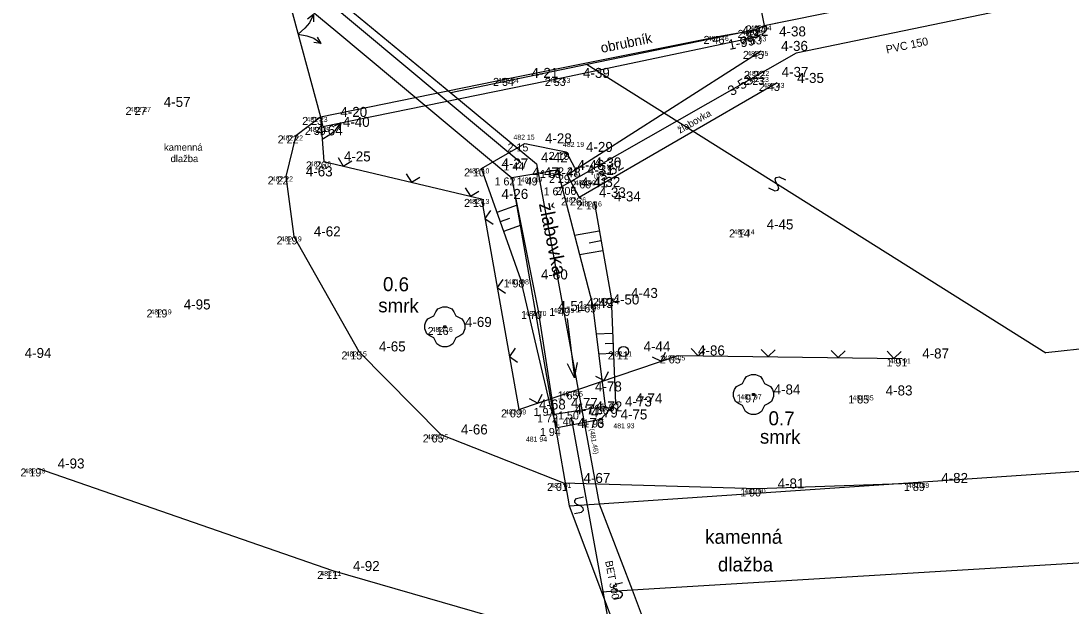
# Model space of a CAD drawing. Extents: x -651478 to -651308, y -994378 to -994071.
# Drawn here: x -651409.01 to -651388.03, y -994292.61 to -994280.91 of the extents above; entities that cross this region are included whole.
import ezdxf

# ---------------------------------------------------------------- set-up
doc = ezdxf.new("R2010")
doc.units = 0
for name, color, linetype in [('13_POPIS_POLOHOPISU', 7, 'Continuous'), ('14_ROZHRANI_PLOCH', 7, 'Continuous'), ('18_TECKY_BODU', 7, 'Continuous'), ('19_CISLA_BODU', 7, 'Continuous'), ('20_REDUKOVANE_VYSKY_BODU', 7, 'Continuous'), ('22_JEDNOTL_STROMY', 7, 'Continuous'), ('23_BREHOVA_CARA', 7, 'Continuous'), ('25_CHODNIKY', 7, 'Continuous'), ('26_PLOTY', 7, 'Continuous'), ('29_PROPUSTKY', 7, 'Continuous'), ('34_KANAL-VEDENI', 7, 'Continuous'), ('52_UPLNE_VYSKY_NADZEMNICH_ZNAKU', 7, 'Continuous'), ('55_SVAHOVE_CARY', 7, 'Continuous'), ('61_UPLNE_VYSKY_BODU', 7, 'Continuous'), ('_KM', 7, 'Continuous'), ('rybnik oprava', 7, 'Continuous')]:
    doc.layers.add(name, color=color, linetype=linetype)

# ---------------------------------------------------------------- blocks, each defined once
blk = doc.blocks.new('POINT_DISPLAY')
blk.add_line((0, 0), (0, 0))
blk = doc.blocks.new('Z58')
for p, q in [((-0.3, 0.4), (-0.16, 0.28)), ((-0.3, 0.4), (-0.24, 0.26)), ((-0.3, 0.4), (-0.16, 0.36)), ((-0.16, 0.28), (-0.08, 0.16)), ((0.08, 0.16), (0.16, 0.28)), ((0.16, 0.28), (0.3, 0.4)), ((0.3, 0.4), (0.16, 0.36)), ((0.3, 0.4), (0.24, 0.26)), ((-0.08, 0.16), (0, 0)), ((0, 0), (0.08, 0.16))]:
    blk.add_line(p, q)
blk = doc.blocks.new('Z212')
for p, q in [((-0.14, 0.14), (0, 0)), ((0, 0), (0.14, 0.14))]:
    blk.add_line(p, q)
blk = doc.blocks.new('Z313')
for p, q in [((-0.34, 0.16), (-0.22, 0.22)), ((-0.22, 0.22), (-0.18, 0.3)), ((-0.18, 0.3), (-0.14, 0.36)), ((-0.14, 0.36), (-0.04, 0.4)), ((-0.04, 0.4), (0.04, 0.4)), ((0.04, 0.4), (0.14, 0.36)), ((0.14, 0.36), (0.18, 0.3)), ((0.18, 0.3), (0.22, 0.22)), ((0.22, 0.22), (0.34, 0.16)), ((-0.4, 0.04), (-0.38, 0.1)), ((-0.4, -0.04), (-0.4, 0.04)), ((-0.38, 0.1), (-0.34, 0.16)), ((-0.02, -0.02), (-0.02, 0.02)), ((-0.02, 0.02), (0.02, 0.02)), ((0.02, 0.02), (0.02, -0.02)), ((0.34, 0.16), (0.38, 0.1)), ((0.38, 0.1), (0.4, 0.04)), ((0.4, 0.04), (0.4, -0.04)), ((-0.36, -0.14), (-0.4, -0.04)), ((-0.3, -0.18), (-0.36, -0.14)), ((-0.22, -0.22), (-0.3, -0.18)), ((0.02, -0.02), (-0.02, -0.02)), ((0.3, -0.18), (0.22, -0.22)), ((0.36, -0.14), (0.3, -0.18)), ((0.4, -0.04), (0.36, -0.14)), ((-0.16, -0.34), (-0.22, -0.22)), ((-0.1, -0.38), (-0.16, -0.34)), ((-0.04, -0.4), (-0.1, -0.38)), ((0.04, -0.4), (-0.04, -0.4)), ((0.1, -0.38), (0.04, -0.4)), ((0.16, -0.34), (0.1, -0.38)), ((0.22, -0.22), (0.16, -0.34))]:
    blk.add_line(p, q)
blk = doc.blocks.new('Z105')
for radius in [0.1, 0.002]:
    blk.add_circle((0, 0), radius)
blk = doc.blocks.new('Z802')
for p, q in [((-0.6, 0), (0.6, 0)), ((0.6, 0), (0.3, 0.1)), ((0.6, 0), (0.3, -0.1))]:
    blk.add_line(p, q)
blk = doc.blocks.new('Z218')
for p, q in [((-0.04, 0.14), (-0.08, 0.1)), ((-0.08, 0.1), (-0.08, 0.06)), ((-0.08, 0.06), (-0.04, 0.02)), ((0.1, 0.16), (-0.04, 0.14)), ((-0.04, 0.02), (0.04, -0.02)), ((0.04, -0.14), (-0.1, -0.16)), ((0.04, -0.02), (0.08, -0.06)), ((0.08, -0.1), (0.04, -0.14)), ((0.08, -0.06), (0.08, -0.1))]:
    blk.add_line(p, q)

msp = doc.modelspace()

# ---------------------------------------------------------------- linework, layer by layer
at = {"layer": '14_ROZHRANI_PLOCH'}
for p, q in [((-651403.52, -994283.2), (-651403.03, -994282.83)), ((-651403.52, -994283.2), (-651403.72, -994284.02)), ((-651403.72, -994284.02), (-651403.56, -994285.22)), ((-651403.56, -994285.22), (-651402.26, -994287.52)), ((-651402.26, -994287.52), (-651400.62, -994289.18)), ((-651400.62, -994289.18), (-651398.17, -994290.15)), ((-651402.78, -994291.91), (-651408.68, -994289.86)), ((-651398.17, -994290.15), (-651394.29, -994290.26)), ((-651394.29, -994290.26), (-651391.02, -994290.15)), ((-651398.36, -994293.18), (-651402.78, -994291.91))]:
    msp.add_line(p, q, dxfattribs=at)
at = {"layer": '23_BREHOVA_CARA'}
for p, q in [((-651394.16, -994281), (-651393.768, -994280.921)), ((-651398.1, -994283.99), (-651394.22, -994281.51)), ((-651393.9, -994282.15), (-651397.86, -994284.44)), ((-651399.2, -994284.04), (-651398.29, -994283.89)), ((-651398.29, -994283.89), (-651397.59, -994286.58)), ((-651398.1, -994283.99), (-651397.86, -994284.44)), ((-651398.67, -994286.71), (-651399.2, -994284.04)), ((-651398.35, -994288.78), (-651398.67, -994286.71)), ((-651397.59, -994286.58), (-651397.34, -994288.62)), ((-651397.34, -994288.62), (-651398.35, -994288.78))]:
    msp.add_line(p, q, dxfattribs=at)
at = {"layer": '25_CHODNIKY'}
for p, q in [((-651394.33, -994281.09), (-651394.16, -994281)), ((-651399.21, -994282.05), (-651395.01, -994281.21)), ((-651394.26, -994281.22), (-651398.18, -994282.05)), ((-651395.01, -994281.21), (-651394.33, -994281.09)), ((-651403.03, -994282.83), (-651399.21, -994282.05)), ((-651398.18, -994282.05), (-651402.98, -994283.03)), ((-651403.03, -994282.83), (-651402.98, -994283.03))]:
    msp.add_line(p, q, dxfattribs=at)
at = {"layer": '26_PLOTY'}
for p, q in [((-651403.92, -994279.52), (-651403.03, -994282.83)), ((-651403.03, -994282.83), (-651402.96, -994283.72)), ((-651402.62, -994282.947), (-651402.756, -994283.015)), ((-651402.729, -994283.093), (-651402.62, -994282.947)), ((-651402.62, -994282.947), (-651402.649, -994283.087)), ((-651402.842, -994283.184), (-651402.729, -994283.093)), ((-651402.995, -994283.275), (-651402.842, -994283.184)), ((-651402.96, -994283.72), (-651399.81, -994284.47)), ((-651399.81, -994284.47), (-651399.06, -994288.68)), ((-651399.06, -994288.68), (-651395.88, -994287.6)), ((-651395.88, -994287.6), (-651391.4, -994287.66))]:
    msp.add_line(p, q, dxfattribs=at)
at = {"layer": '29_PROPUSTKY'}
for p, q in [((-651407.5, -994276.66), (-651399.02, -994283.74)), ((-651398.02, -994288.84), (-651396.42, -994297.57))]:
    msp.add_line(p, q, dxfattribs=at)
at = {"layer": '34_KANAL-VEDENI'}
for p, q in [((-651389.625, -994280.75), (-651393.522, -994281.556)), ((-651393.522, -994281.556), (-651398.24, -994284.25))]:
    msp.add_line(p, q, dxfattribs=at)
at = {"layer": '55_SVAHOVE_CARY'}
for p, q in [((-651399.81, -994283.86), (-651398.94, -994283.36)), ((-651398.94, -994283.36), (-651398.12, -994283.53)), ((-651398.12, -994283.53), (-651397.95, -994283.84)), ((-651399.02, -994286.08), (-651399.81, -994283.86)), ((-651399.498, -994284.736), (-651399.091, -994284.591)), ((-651397.56, -994284.52), (-651397.22, -994286.45)), ((-651399.431, -994284.924), (-651399.241, -994284.856)), ((-651399.364, -994285.112), (-651399.012, -994284.987)), ((-651397.455, -994285.114), (-651397.949, -994285.201)), ((-651397.421, -994285.311), (-651397.659, -994285.353)), ((-651397.386, -994285.508), (-651397.848, -994285.59)), ((-651398.42, -994288.65), (-651399.02, -994286.08)), ((-651397.22, -994286.45), (-651397.13, -994288.56)), ((-651397.19, -994287.161), (-651397.517, -994287.175)), ((-651397.181, -994287.361), (-651397.337, -994287.368)), ((-651397.173, -994287.561), (-651397.468, -994287.574)), ((-651397.13, -994288.56), (-651397.43, -994288.88)), ((-651398.29, -994289.05), (-651398.42, -994288.65)), ((-651397.43, -994288.88), (-651398.29, -994289.05))]:
    msp.add_line(p, q, dxfattribs=at)
at = {"layer": '_KM'}
for p, q in [((-651405.68, -994278.64), (-651402.72, -994281.11)), ((-651402.46, -994280.67), (-651400.42, -994282.35)), ((-651402.72, -994281.11), (-651399.2, -994284.05)), ((-651394.33, -994281.09), (-651397.7, -994281.78)), ((-651397.7, -994281.78), (-651400.42, -994282.35)), ((-651397.7, -994281.78), (-651388.53, -994287.55)), ((-651400.42, -994282.35), (-651398.71, -994283.77)), ((-651342.04, -994282.52), (-651388.53, -994287.55)), ((-651398.71, -994283.77), (-651397.46, -994290.57)), ((-651399.2, -994284.05), (-651398.06, -994290.61)), ((-651397.46, -994290.57), (-651361.24, -994288.11)), ((-651396.8, -994292.29), (-651361.1, -994290.11)), ((-651398.06, -994290.61), (-651397.46, -994290.57)), ((-651398.06, -994290.61), (-651397.41, -994292.33)), ((-651397.46, -994290.57), (-651396.8, -994292.29)), ((-651397.41, -994292.33), (-651396.8, -994292.29)), ((-651397.41, -994292.33), (-651395.36, -994297.7)), ((-651396.8, -994292.29), (-651394.77, -994297.58))]:
    msp.add_line(p, q, dxfattribs=at)
at = {"layer": 'rybnik oprava'}
for p, q in [((-651395.81, -994272.73), (-651394.16, -994281)), ((-651394.16, -994281), (-651368.14, -994275.72))]:
    msp.add_line(p, q, dxfattribs=at)

# ---------------------------------------------------------------- block references
at = {"layer": '13_POPIS_POLOHOPISU'}
msp.add_blockref('Z105', (-651396.97, -994287.52), dxfattribs=at)
at = {"layer": '18_TECKY_BODU'}
for p in [(-651394.16, -994281), (-651395.01, -994281.21), (-651394.33, -994281.09), (-651394.26, -994281.22), (-651394.22, -994281.51), (-651394.2, -994281.91), (-651399.21, -994282.05), (-651398.18, -994282.05), (-651394.21, -994282.03), (-651393.9, -994282.15), (-651406.56, -994282.63), (-651403.03, -994282.83), (-651402.98, -994283.03), (-651403.52, -994283.2), (-651398.94, -994283.36), (-651398.12, -994283.53), (-651402.96, -994283.72), (-651399.02, -994283.74), (-651399.81, -994283.86), (-651398.29, -994283.89), (-651398.1, -994283.99), (-651397.95, -994283.84), (-651403.72, -994284.02), (-651399.2, -994284.04), (-651398.76, -994284.04), (-651397.67, -994284.1), (-651398.22, -994284.24), (-651397.97, -994284.23), (-651399.81, -994284.47), (-651397.86, -994284.44), (-651397.56, -994284.52), (-651403.56, -994285.22), (-651394.51, -994285.08), (-651399.02, -994286.08), (-651397.22, -994286.45), (-651406.16, -994286.68), (-651398.67, -994286.71), (-651398.11, -994286.65), (-651397.59, -994286.58), (-651400.54, -994287.03), (-651402.26, -994287.52), (-651396.97, -994287.52), (-651395.88, -994287.6), (-651391.4, -994287.66), (-651397.94, -994288.32), (-651394.37, -994288.38), (-651392.13, -994288.4), (-651397.34, -994288.62), (-651397.13, -994288.56), (-651399.06, -994288.68), (-651398.42, -994288.65), (-651398.35, -994288.78), (-651398.02, -994288.84), (-651397.93, -994288.72), (-651398.29, -994289.05), (-651397.43, -994288.88), (-651400.62, -994289.18), (-651408.68, -994289.86), (-651398.17, -994290.15), (-651394.29, -994290.26), (-651391.02, -994290.15), (-651402.78, -994291.91)]:
    msp.add_blockref('POINT_DISPLAY', p, dxfattribs=at)
at = {"layer": '22_JEDNOTL_STROMY'}
for p in [(-651400.54, -994287.03), (-651394.37, -994288.38)]:
    msp.add_blockref('Z313', p, dxfattribs=at)
at = {"layer": '23_BREHOVA_CARA', "rotation": -83.01330000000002}
msp.add_blockref('Z802', (-651398.025, -994287.455), dxfattribs=at)
at = {"layer": '26_PLOTY'}
for name, p, rotation in [('Z58', (-651403.475, -994281.175), -74.95010000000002), ('Z212', (-651402.571, -994283.813), -13.399999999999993), ('Z212', (-651401.209, -994284.137), -13.399999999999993), ('Z212', (-651400.029, -994284.418), -13.392500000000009), ('Z212', (-651399.74, -994284.864), -79.89999999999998), ('Z212', (-651399.494, -994286.242), -79.89999999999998), ('Z212', (-651399.249, -994287.62), -79.89999999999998), ('Z212', (-651396.219, -994287.715), 18.7587), ('Z212', (-651395.48, -994287.605), -0.8000000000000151), ('Z212', (-651394.08, -994287.624), -0.8000000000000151), ('Z212', (-651392.68, -994287.643), -0.8000000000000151), ('Z212', (-651391.564, -994287.658), -0.767299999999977), ('Z212', (-651397.356, -994288.101), 18.8), ('Z212', (-651398.681, -994288.551), 18.8)]:
    msp.add_blockref(name, p, dxfattribs=dict(at, rotation=rotation))
at = {"layer": '_KM'}
for p, rotation in [((-651393.903, -994284.169), 147.8208), ((-651397.86, -994290.597), -176.18590000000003), ((-651397.077, -994292.308), -176.24830000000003)]:
    msp.add_blockref('Z218', p, dxfattribs=dict(at, rotation=rotation))

# ---------------------------------------------------------------- texts
at = {"layer": '13_POPIS_POLOHOPISU'}
for s, height, rotation, p in [('obrubník', 0.2, 11.5393, (-651397.406, -994281.551)), ('žlabovka', 0.14, 30.0401, (-651395.842, -994283.167)), ('žlabovka', 0.28, 281.2274, (-651398.664, -994284.569)), ('0.6', 0.28, 359.2327, (-651401.78, -994286.312)), ('smrk', 0.28, 359.2327, (-651401.875, -994286.737)), ('0.7', 0.28, 359.2327, (-651394.074, -994288.995)), ('smrk', 0.28, 359.2327, (-651394.246, -994289.363))]:
    msp.add_text(s, height=height, rotation=rotation, dxfattribs=at).set_placement(p)
for s, height, p in [('kamenná', 0.14, (-651406.155, -994283.507)), ('dlažba', 0.14, (-651406.023, -994283.734)), ('kamenná', 0.28, (-651395.339, -994291.366)), ('dlažba', 0.28, (-651395.083, -994291.92))]:
    msp.add_text(s, height=height, dxfattribs=at).set_placement(p)
at = {"layer": '19_CISLA_BODU'}
for s, p in [('4-22', (-651394.61, -994281.21)), ('4-38', (-651393.86, -994281.22)), ('4-36', (-651393.82, -994281.51)), ('4-21', (-651398.81, -994282.05)), ('4-39', (-651397.78, -994282.05)), ('4-37', (-651393.81, -994282.03)), ('4-35', (-651393.5, -994282.15)), ('4-57', (-651406.16, -994282.63)), ('4-20', (-651402.63, -994282.83)), ('4-40', (-651402.58, -994283.03)), ('4-64', (-651403.12, -994283.2)), ('4-28', (-651398.54, -994283.36)), ('4-29', (-651397.72, -994283.53)), ('4-25', (-651402.56, -994283.72)), ('4-42', (-651398.62, -994283.74)), ('4-27', (-651399.41, -994283.86)), ('4-46', (-651397.89, -994283.89)), ('4-31', (-651397.7, -994283.99)), ('4-30', (-651397.55, -994283.84)), ('4-63', (-651403.32, -994284.02)), ('4-47', (-651398.8, -994284.04)), ('4-48', (-651398.36, -994284.04)), ('4-41', (-651397.82, -994284.24)), ('4-32', (-651397.57, -994284.23)), ('4-26', (-651399.41, -994284.47)), ('4-33', (-651397.46, -994284.44)), ('4-34', (-651397.16, -994284.52)), ('4-62', (-651403.16, -994285.22)), ('4-45', (-651394.11, -994285.08)), ('4-80', (-651398.62, -994286.08)), ('4-43', (-651396.82, -994286.45)), ('4-95', (-651405.76, -994286.68)), ('4-51', (-651398.27, -994286.71)), ('4-49', (-651397.71, -994286.65)), ('4-50', (-651397.19, -994286.58)), ('4-69', (-651400.14, -994287.03)), ('4-65', (-651401.86, -994287.52)), ('4-44', (-651396.57, -994287.52)), ('4-94', (-651408.94, -994287.65)), ('4-86', (-651395.48, -994287.6)), ('4-87', (-651391, -994287.66)), ('4-78', (-651397.54, -994288.32)), ('4-84', (-651393.97, -994288.38)), ('4-83', (-651391.73, -994288.4)), ('4-73', (-651396.94, -994288.62)), ('4-74', (-651396.73, -994288.56)), ('4-68', (-651398.66, -994288.68)), ('4-77', (-651398.02, -994288.65)), ('4-71', (-651397.95, -994288.78)), ('4-72', (-651397.53, -994288.72)), ('4-79', (-651397.62, -994288.84)), ('4-75', (-651397.03, -994288.88)), ('4-66', (-651400.22, -994289.18)), ('4-76', (-651397.89, -994289.05)), ('4-93', (-651408.28, -994289.86)), ('4-67', (-651397.77, -994290.15)), ('4-81', (-651393.89, -994290.26)), ('4-82', (-651390.62, -994290.15)), ('4-92', (-651402.38, -994291.91))]:
    msp.add_text(s, height=0.2, dxfattribs=at).set_placement(p)
for s, rotation, p in [('1-99', 11.5922, (-651394.855, -994281.492)), ('3-53', 32.257, (-651394.808, -994282.42)), ('3-52', 32.257, (-651397.401, -994284.131))]:
    msp.add_text(s, height=0.2, rotation=rotation, dxfattribs=at).set_placement(p)
at = {"layer": '20_REDUKOVANE_VYSKY_BODU'}
for s, p in [(' 2 44', (-651394.587, -994281.16)), (' 2 46', (-651395.429, -994281.37)), (' 2 49', (-651394.749, -994281.25)), (' 2 63', (-651394.683, -994281.38)), (' 2 45', (-651394.643, -994281.67)), (' 2 22', (-651394.623, -994282.07)), (' 2 34', (-651399.637, -994282.21)), (' 2 53', (-651398.603, -994282.21)), (' 2 23', (-651394.633, -994282.19)), (' 2 43', (-651394.323, -994282.31)), (' 2 27', (-651406.983, -994282.79)), (' 2 23', (-651403.453, -994282.99)), (' 2 39', (-651403.399, -994283.19)), (' 2 22', (-651403.943, -994283.36)), (' 2 15', (-651399.348, -994283.52)), (' 2 19', (-651398.524, -994283.69)), (' 2 26', (-651403.379, -994283.88)), (' 1 44', (-651399.431, -994283.9)), (' 2 10', (-651400.218, -994284.02)), (' 1 58', (-651398.698, -994284.05)), (' 2 29', (-651398.519, -994284.15)), (' 2 21', (-651398.339, -994284)), (' 2 22', (-651404.143, -994284.18)), (' 1 62', (-651399.608, -994284.2)), (' 1 49', (-651399.164, -994284.2)), (' 2 09', (-651398.089, -994284.26)), (' 1 67', (-651398.628, -994284.4)), (' 2 06', (-651398.389, -994284.39)), (' 2 13', (-651400.218, -994284.63)), (' 2 26', (-651398.279, -994284.6)), (' 2 16', (-651397.964, -994284.68)), (' 2 19', (-651403.964, -994285.38)), (' 2 14', (-651394.921, -994285.24)), (' 1 98', (-651399.428, -994286.24)), (' 2 02', (-651397.643, -994286.61)), (' 2 19', (-651406.564, -994286.84)), (' 1 70', (-651399.078, -994286.87)), (' 1 49', (-651398.514, -994286.81)), (' 1 69', (-651397.994, -994286.74)), (' 2 16', (-651400.944, -994287.19)), (' 2 15', (-651402.668, -994287.68)), (' 2 11', (-651397.343, -994287.68)), (' 2 05', (-651396.303, -994287.76)), (' 1 91', (-651391.773, -994287.82)), (' 1 65', (-651398.348, -994288.48)), (' 1 97', (-651394.778, -994288.54)), (' 1 85', (-651392.538, -994288.56)), (' 1 66', (-651397.744, -994288.78)), (' 1 91', (-651397.503, -994288.72)), (' 2 09', (-651399.479, -994288.84)), (' 1 97', (-651398.828, -994288.81)), (' 1 72', (-651398.758, -994288.94)), (' 1 46', (-651398.424, -994289)), (' 1 50', (-651398.338, -994288.88)), (' 1 94', (-651398.701, -994289.21)), (' 1 93', (-651397.838, -994289.04)), (' 2 05', (-651401.043, -994289.34)), (' 2 19', (-651409.084, -994290.02)), (' 2 01', (-651398.559, -994290.31)), (' 1 90', (-651394.698, -994290.42)), (' 1 89', (-651391.424, -994290.31)), (' 2 11', (-651403.153, -994292.07))]:
    msp.add_text(s, height=0.16, dxfattribs=at).set_placement(p)
at = {"layer": '29_PROPUSTKY'}
msp.add_text('BET 300', height=0.15, rotation=280.3857, dxfattribs=at).set_placement((-651397.338, -994291.717))
at = {"layer": '34_KANAL-VEDENI'}
msp.add_text('PVC 150', height=0.16, rotation=11.6948, dxfattribs=at).set_placement((-651391.707, -994281.563))
at = {"layer": '52_UPLNE_VYSKY_NADZEMNICH_ZNAKU'}
for s, rotation, p in [('(481.67)', 29.723, (-651397.535, -994284.09)), ('(481.46)', 280.3857, (-651397.653, -994289.074))]:
    msp.add_text(s, height=0.1, rotation=rotation, dxfattribs=at).set_placement(p)
at = {"layer": '61_UPLNE_VYSKY_BODU'}
for s, p in [('482 44 ', (-651394.436, -994281.1)), ('482 46 ', (-651395.288, -994281.31)), ('482 49 ', (-651394.608, -994281.19)), ('482 63 ', (-651394.538, -994281.32)), ('482 45 ', (-651394.497, -994281.61)), ('482 22 ', (-651394.48, -994282.01)), ('482 34 ', (-651399.486, -994282.15)), ('482 53 ', (-651398.457, -994282.15)), ('482 23 ', (-651394.488, -994282.13)), ('482 43 ', (-651394.176, -994282.25)), ('482 27 ', (-651406.839, -994282.73)), ('482 23 ', (-651403.308, -994282.93)), ('482 39 ', (-651403.258, -994283.13)), ('482 22 ', (-651403.8, -994283.3)), ('482 15 ', (-651399.17, -994283.285)), ('482 19 ', (-651398.18, -994283.431)), ('482 26 ', (-651403.24, -994283.82)), ('482 10 ', (-651400.074, -994283.96)), ('482 22 ', (-651404, -994284.12)), ('481 49 ', (-651399.023, -994284.14)), ('482 09 ', (-651397.949, -994284.2)), ('482 13 ', (-651400.073, -994284.57)), ('482 26 ', (-651398.14, -994284.54)), ('482 16 ', (-651397.825, -994284.62)), ('482 19 ', (-651403.825, -994285.32)), ('482 14 ', (-651394.773, -994285.18)), ('481 98 ', (-651399.284, -994286.18)), ('482 02 ', (-651397.499, -994286.55)), ('482 19 ', (-651406.425, -994286.78)), ('481 70 ', (-651398.933, -994286.81)), ('481 49 ', (-651398.373, -994286.75)), ('481 69 ', (-651397.855, -994286.68)), ('482 16 ', (-651400.805, -994287.13)), ('482 15 ', (-651402.524, -994287.62)), ('482 11 ', (-651397.221, -994287.62)), ('482 05 ', (-651396.158, -994287.7)), ('481 91 ', (-651391.651, -994287.76)), ('481 65 ', (-651398.204, -994288.42)), ('481 97 ', (-651394.634, -994288.48)), ('481 85 ', (-651392.393, -994288.5)), ('482 09 ', (-651399.339, -994288.78)), ('481 93 ', (-651397.173, -994289.057)), ('482 05 ', (-651400.898, -994289.28)), ('481 94 ', (-651398.921, -994289.324)), ('482 19 ', (-651408.945, -994289.96)), ('482 01 ', (-651398.434, -994290.25)), ('481 90 ', (-651394.554, -994290.36)), ('481 89 ', (-651391.284, -994290.25)), ('482 11 ', (-651403.031, -994292.01))]:
    msp.add_text(s, height=0.1, dxfattribs=at).set_placement(p)

doc.saveas('drawing.dxf')
